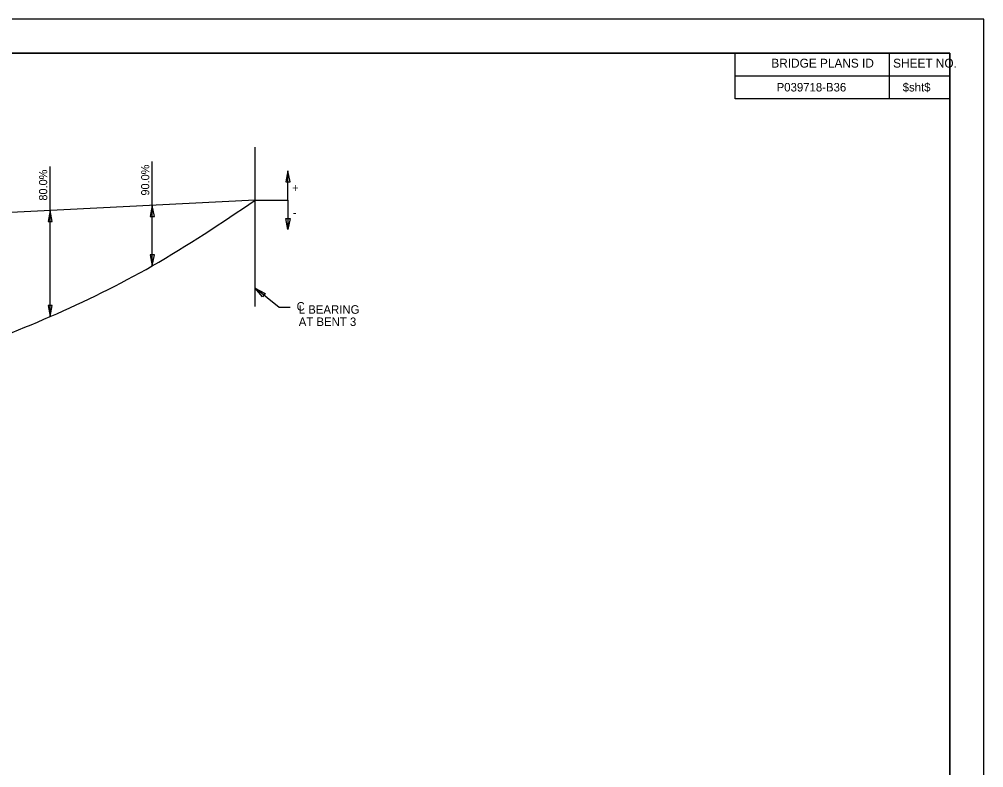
# Model space of a CAD drawing. Extents: x -125.5 to -89.4, y -5.1 to 16.9.
# Drawn here: x -103.71 to -89.53, y 5.93 to 16.93 of the extents above; entities that cross this region are included whole.
import ezdxf

# ---------------------------------------------------------------- set-up
doc = ezdxf.new("R2010")
doc.units = 0
for name, color, linetype in [('BR_AUTO DIMENSION', 7, 'Continuous'), ('BR_BORDER LINES', 7, 'Continuous'), ('BR_CENTER LINES', 7, 'Continuous'), ('BR_TABLE LINES', 7, 'Continuous'), ('BR_TEXT', 7, 'Continuous'), ('Level 31', 7, 'Continuous')]:
    doc.layers.add(name, color=color, linetype=linetype)

msp = doc.modelspace()

# ---------------------------------------------------------------- linework, layer by layer
at = {"layer": 'BR_AUTO DIMENSION'}
for p, q in [((-100.24, 14.275), (-99.76, 14.275)), ((-99.888, 12.7), (-100.24, 12.981)), ((-99.728, 12.7), (-99.888, 12.7))]:
    msp.add_line(p, q, dxfattribs=at)
for points in [[(-99.728, 14.546), (-99.76, 14.708), (-99.791, 14.546)], [(-101.722, 14.037), (-101.753, 14.199), (-101.785, 14.037)], [(-103.222, 13.962), (-103.253, 14.124), (-103.285, 13.962)], [(-99.728, 14.004), (-99.76, 13.842), (-99.791, 14.004)], [(-101.785, 13.472), (-101.753, 13.309), (-101.722, 13.472)], [(-100.131, 12.856), (-100.24, 12.981), (-100.092, 12.906)], [(-103.285, 12.727), (-103.253, 12.564), (-103.222, 12.727)]]:
    msp.add_lwpolyline(points, close=True, dxfattribs=at)
at = {"layer": 'BR_BORDER LINES'}
for p, q in [((-90.033, 16.434), (-123.699, 16.434)), ((-93.186, 15.767), (-93.186, 16.434)), ((-90.919, 15.767), (-90.919, 16.434)), ((-90.033, -4.566), (-90.033, 16.434)), ((-93.186, 16.104), (-90.033, 16.104)), ((-90.919, 16.104), (-90.033, 16.104)), ((-90.033, 15.767), (-93.186, 15.767))]:
    msp.add_line(p, q, dxfattribs=at)
at = {"layer": 'BR_CENTER LINES'}
msp.add_line((-100.24, 12.713), (-100.24, 15.052), dxfattribs=at)
at = {"layer": 'BR_TABLE LINES'}
for p, q in [((-103.253, 12.564), (-103.253, 14.769)), ((-101.753, 13.309), (-101.753, 14.844)), ((-99.76, 14.275), (-99.76, 14.708)), ((-100.24, 14.275), (-115.253, 13.524)), ((-99.76, 14.275), (-99.76, 13.842))]:
    msp.add_line(p, q, dxfattribs=at)
msp.add_lwpolyline([(-123.699, 16.434), (-90.033, 16.434), (-90.033, -4.566), (-123.699, -4.566)], close=True, dxfattribs=at)
msp.add_spline([(-115.253, 13.524), (-113.753, 12.379), (-112.253, 11.644), (-110.753, 11.249), (-109.253, 11.134), (-107.753, 11.249), (-106.253, 11.534), (-104.753, 11.979), (-103.253, 12.564), (-101.753, 13.309), (-100.24, 14.275)], degree=3, dxfattribs=at)
at = {"layer": 'Level 31'}
msp.add_lwpolyline([(-125.533, -5.066), (-89.533, -5.066), (-89.533, 16.934), (-125.533, 16.934)], close=True, dxfattribs=at)

# ---------------------------------------------------------------- texts
at = {"layer": 'BR_AUTO DIMENSION'}
for s, p in [('C', (-99.632, 12.652)), ('L BEARING', (-99.6, 12.606)), ('AT BENT 3', (-99.6, 12.426))]:
    msp.add_text(s, height=0.125, dxfattribs=at).set_placement(p)
at = {"layer": 'BR_TEXT'}
for s, height, p in [('BRIDGE PLANS ID', 0.13, (-92.654, 16.224)), ('SHEET NO.', 0.13, (-90.864, 16.224)), ('P039718-B36', 0.125, (-92.576, 15.873)), ('$sht$', 0.125, (-90.724, 15.873)), ('-', 0.12, (-99.689, 14.034))]:
    msp.add_text(s, height=height, dxfattribs=at).set_placement(p)
for s, rotation, p in [('90.0%', 90, (-101.797, 14.343)), ('80.0%', 90, (-103.297, 14.269)), ('+', 360, (-99.698, 14.396))]:
    msp.add_text(s, height=0.12, rotation=rotation, dxfattribs=at).set_placement(p)

doc.saveas('drawing.dxf')
